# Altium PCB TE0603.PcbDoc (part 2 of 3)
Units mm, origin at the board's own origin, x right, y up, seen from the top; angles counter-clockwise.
Board outline 115 x 70 mm, 4 copper layers (L 01 (Top), L 02, L 03, L 04 (Bot)), stack 1.564 mm thick; 86 components, 166 nets, 587 pads, 211 vias.
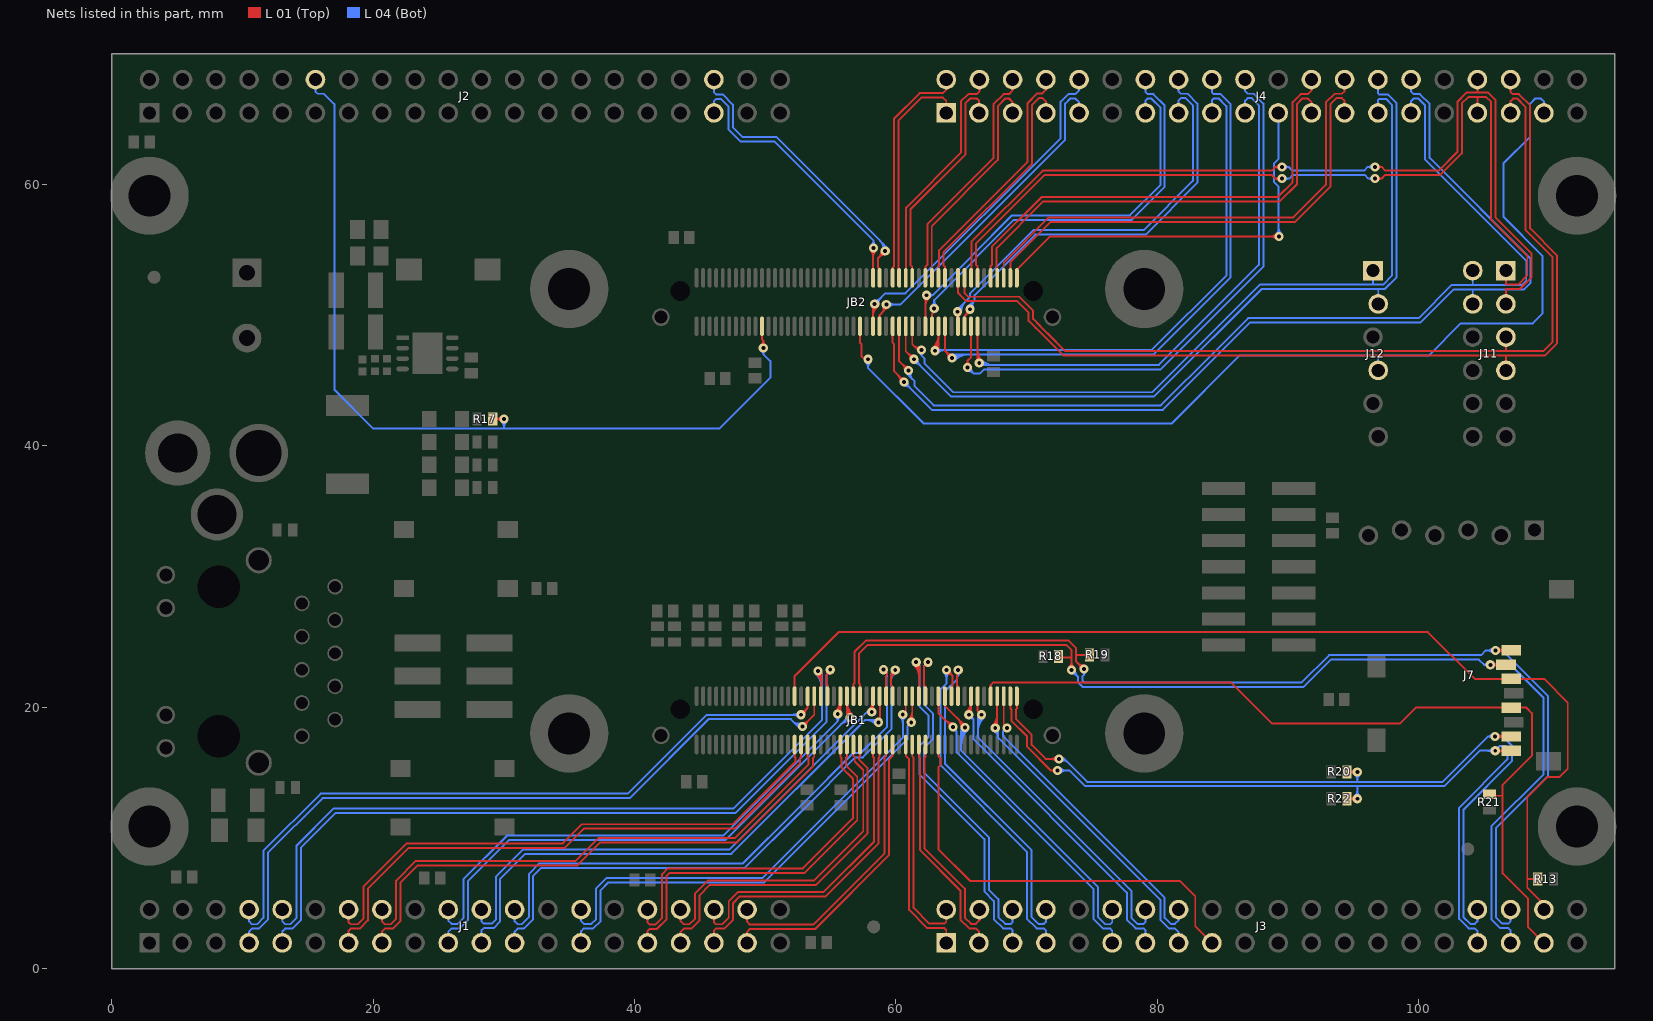
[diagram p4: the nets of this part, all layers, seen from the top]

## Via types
v1: diameter 0.7, hole 0.3, L 01 (Top) to L 04 (Bot), 211 vias

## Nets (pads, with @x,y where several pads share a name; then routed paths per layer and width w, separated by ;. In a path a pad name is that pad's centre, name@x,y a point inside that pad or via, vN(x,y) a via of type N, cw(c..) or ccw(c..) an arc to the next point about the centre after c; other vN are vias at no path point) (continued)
B2B_B0_L36_P: J4.37 J12.4 JB2.52 | length 82.7
  L 01 (Top) w0.15: JB2.52@57.25,48.85 57.25,47.894 57.365,47.78 57.365,46.86 57.6,46.625 v1(57.875,46.625) v1@57.865,46.635
  L 04 (Bot) w0.15: v1@57.681,46.431 cw(c57.211,45.961) 57.875,45.961 cw(c58.539,45.961) v1@58.069,46.431 ; v1(57.875,46.625) 57.875,45.95 62.115,41.71 81.091,41.71 86.281,46.9 96.9,46.9 ; J12.4@96.9,45.78 96.9,46.9 ; J4.37@109.571,65.479 109.571,66.354 109.35,66.575 108.9,66.575 108.515,66.19 108.515,63.665 106.49,61.64 106.49,57.51 109.465,54.535 109.465,50.109 108.731,49.375 103.231,49.375 100.756,46.9 96.9,46.9
B2B_B0_L37_N: J2.35 JB2.55 | length 23.6
  L 01 (Top) w0.15: v1@58.081,54.931 cw(c57.671,54.521) 58.25,54.521 ; JB2.55@58.25,52.85 v1@58.25,54.925 ; 58.25,54.401 cw(c58.999,54.401) v1@58.469,54.931 ; 58.25,54.763 cw(c58.637,54.763) v1@58.363,55.037
  L 04 (Bot) w0.15: J2.35@46.071,65.479 46.071,66.371 46.25,66.55 46.6,66.55 47.185,65.965 47.185,64.219 48.129,63.275 50.725,63.275 58.275,55.725 ; v1@58.095,55.333 ccw(c57.758,55.725) 58.275,55.725 ; v1(58.275,55.125) 58.275,55.725 ; v1@58.455,55.333 cw(c58.792,55.725) 58.275,55.725
B2B_B0_L37_P: J2.36 JB2.57 | length 25.6
  L 01 (Top) w0.15: JB2.57@58.75,52.55 JB2.57@58.75,52.85 58.711,52.889 58.711,53.575 58.635,53.652 58.635,54.36 v1(59.178,54.903) ; v1@58.903,54.903 cw(c58.239,54.903) 58.708,54.433 cw(c59.178,53.964) v1@59.178,54.628
  L 04 (Bot) w0.15: J2.36@46.071,68.019 46.071,67.069 46.25,66.89 46.741,66.89 47.525,66.106 47.525,64.359 48.269,63.615 50.866,63.615 58.765,55.716 ; 58.765,55.71 v1@59.228,55.247 ; 58.787,55.688 cw(c58.126,55.028) v1@59.054,54.917 ; 59.005,55.47 cw(c58.516,54.981) v1@59.203,54.9 ; 59.224,55.251 cw(c58.907,54.935) v1@59.352,54.882
B2B_B0_L38_N: J4.2 JB2.61 | length 18.2
  L 01 (Top) w0.15: JB2.61@59.75,52.55 59.75,53.63 59.868,53.748 59.868,54.257 59.865,54.26 59.865,65.046 61.809,66.99 63.6,66.99 63.851,67.241 J4.2@63.851,68.019
B2B_B0_L38_P: J4.1 JB2.63 | length 17.8
  L 01 (Top) w0.15: JB2.63@60.25,52.55 60.25,53.383 60.205,53.428 60.205,53.604 60.208,53.607 60.208,54.398 60.205,54.401 60.205,64.905 61.95,66.65 63.6,66.65 63.851,66.399 J4.1@63.851,65.479
B2B_B0_L49_N: J4.9 JB2.58 | length 28.6
  L 01 (Top) w0.15: JB2.58@58.75,48.85 58.75,50 59.265,50.515 v1(59.265,50.823) ; 58.904,50.154 ccw(c58.544,50.514) v1@59.012,50.715 ; 59.061,50.311 ccw(c58.764,50.608) v1@59.15,50.774 ; 59.218,50.468 ccw(c58.983,50.702) v1@59.288,50.833
  L 04 (Bot) w0.15: v1(59.265,50.823) 60.354,50.823 72.94,63.409 72.94,66.19 73.325,66.575 73.725,66.575 74.011,66.289 J4.9@74.011,65.479 ; v1@59.459,50.629 cw(c59.929,50.159) 59.929,50.823 cw(c59.929,51.487) v1@59.459,51.018
B2B_B0_L49_P: J4.10 JB2.56 | length 29.6
  L 01 (Top) w0.15: v1@58.181,50.656 cw(c58.012,50.487) 58.25,50.487 ; JB2.56@58.25,48.85 58.25,50.725 v1(58.375,50.85) ; JB2.56@58.25,49.885 cw(c59.34,49.885) v1@58.569,50.656 ; 58.25,50.247 cw(c58.978,50.247) v1@58.463,50.762
  L 04 (Bot) w0.15: v1(58.375,50.85) 59.19,51.665 60.715,51.665 72.6,63.55 72.6,66.331 73.184,66.915 73.725,66.915 74.011,67.201 J4.10@74.011,68.019 ; v1@58.375,51.125 ccw(c58.375,51.789) 58.844,51.319 ccw(c59.314,50.85) v1@58.65,50.85
B2B_B0_L50_N: J4.4 JB2.65 | length 18.2
  L 01 (Top) w0.15: JB2.65@60.75,52.55 60.75,53.383 60.773,53.406 60.773,58.223 64.975,62.425 64.975,66.356 65.534,66.915 66.2,66.915 66.391,67.106 J4.4@66.391,68.019
B2B_B0_L50_P: J4.3 JB2.67 | length 17.7
  L 01 (Top) w0.15: JB2.67@61.25,52.55 JB2.67@61.25,52.85 61.25,53.688 61.113,53.825 61.113,58.082 65.315,62.284 65.315,66.215 65.675,66.575 66.2,66.575 66.351,66.424 J4.3@66.351,65.479
B2B_B0_L51_N: J4.6 JB2.71 | length 18.5
  L 01 (Top) w0.15: JB2.71@62.25,52.85 62.25,53.7 62.4,53.85 62.4,56.956 67.46,62.016 67.46,66.141 68.234,66.915 68.65,66.915 68.931,67.196 J4.6@68.931,68.019 ; JB2.71@62.25,52.55 JB2.71@62.25,52.85
B2B_B0_L51_P: J4.5 JB2.73 | length 17.9
  L 01 (Top) w0.15: JB2.73@62.75,52.55 62.75,53.383 62.74,53.393 62.74,56.815 67.8,61.875 67.8,66 68.375,66.575 68.65,66.575 68.931,66.294 J4.5@68.931,65.479
B2B_B0_L62_N: J4.29 J11.2 JB2.64 | length 79.1
  L 01 (Top) w0.15: JB2.64@60.25,48.85 60.25,46.48 v1(60.953,45.777) ; v1@60.678,45.777 ccw(c60.014,45.777) 60.484,46.247 ccw(c60.953,46.716) v1@60.953,46.052
  L 04 (Bot) w0.15: v1@60.932,45.79 ccw(c61.205,45.623) 60.978,45.397 ; v1(60.953,45.777) 60.953,45.422 ; v1@61.06,45.712 ccw(c61.371,45.521) 61.113,45.262 ; v1@61.187,45.634 ccw(c61.538,45.419) 61.247,45.128 ; J4.29@99.411,65.479 99.411,66.386 99.6,66.575 99.95,66.575 100.485,66.04 100.485,61.896 108.225,54.156 108.225,52.625 107.915,52.315 102.54,52.315 99.99,49.765 86.94,49.765 84.34,47.165 80.275,43.1 62.886,43.1 61.425,44.561 61.425,44.95 60.953,45.422 ; 104.13,52.37 J11.2@104.13,53.4 ; 60.953,45.422 cw(c61.045,45.422) 61.022,45.511 ccw(c61.045,45.422) 60.953,45.422 ; 60.953,45.422 ccw(c60.861,45.422) 60.884,45.511 cw(c60.861,45.422) 60.953,45.422
B2B_B0_L62_P: J4.30 J11.4 JB2.62 | length 80.4
  L 01 (Top) w0.15: JB2.62@59.75,48.85 59.75,47.894 59.865,47.78 59.865,45.71 60.482,45.093 60.482,45.068 60.628,44.922 v1(60.628,44.877) ; 60.109,45.466 cw(c59.52,44.877) v1@60.353,44.877 ; 60.278,45.297 ccw(c60.628,45.647) v1@60.628,45.152 ; 60.365,45.21 cw(c60.033,44.877) v1@60.503,44.877
  L 04 (Bot) w0.15: v1@60.628,44.602 cw(c60.628,43.938) 61.097,44.408 cw(c61.567,44.877) v1@60.903,44.877 ; v1(60.628,44.877) 62.745,42.76 80.416,42.76 87.081,49.425 100.131,49.425 102.681,51.975 104.125,51.975 ; J4.30@99.411,68.019 99.411,67.104 99.6,66.915 100.091,66.915 100.825,66.181 100.825,62.037 108.565,54.297 108.565,52.484 108.056,51.975 104.125,51.975 ; J11.4@104.13,50.86 104.13,51.97 104.125,51.975
B2B_B0_L63_N: J4.8 JB2.75 | length 19.1
  L 01 (Top) w0.15: JB2.75@63.25,52.55 JB2.75@63.25,52.85 63.25,53.805 63.295,53.85 63.295,54.945 63.31,54.96 70.075,61.725 70.075,66.231 70.809,66.965 71.2,66.965 71.471,67.236 J4.8@71.471,68.019
B2B_B0_L63_P: J4.7 JB2.77 | length 18.7
  L 01 (Top) w0.15: JB2.77@63.75,52.55 JB2.77@63.75,52.85 63.75,53.71 63.635,53.825 63.635,54.804 70.415,61.584 70.415,66.09 70.95,66.625 71.2,66.625 71.471,66.354 J4.7@71.471,65.479
B2B_B0_L64_N: J4.36 J11.7 JB2.81 | length 72.5
  L 01 (Top) w0.15: JB2.81@64.75,52.55 64.75,51.708 64.885,51.573 64.885,51.567 65.384,51.067 69.277,51.067 70.155,50.189 70.155,49.57 70.695,49.03 70.695,49.02 71.445,48.27 71.455,48.27 72.825,46.9 106.65,46.9 ; J11.7@106.67,45.78 106.67,46.88 106.65,46.9 ; J4.36@107.031,68.019 107.031,67.069 107.185,66.915 107.662,66.915 108.515,66.062 108.515,56.64 110.575,54.581 110.575,47.819 109.656,46.9 106.65,46.9
B2B_B0_L64_P: J4.35 J11.5 JB2.83 | length 70.7
  L 01 (Top) w0.15: JB2.83@65.25,52.55 65.25,51.682 65.525,51.407 69.418,51.407 70.495,50.33 70.495,49.711 71.035,49.171 71.035,49.161 71.586,48.61 71.596,48.61 72.966,47.24 106.675,47.24 ; J11.5@106.67,48.32 106.67,47.245 106.675,47.24 ; J4.35@107.031,65.479 107.031,66.381 107.225,66.575 107.521,66.575 108.175,65.921 108.175,56.5 110.235,54.44 110.235,47.96 109.515,47.24 106.675,47.24
B2B_B0_L65_N: J4.34 J11.3 JB2.85 | length 72.7
  L 01 (Top) w0.15: JB2.85@65.75,52.55 65.795,52.595 65.795,53.704 65.773,53.726 65.773,55.604 71.234,61.065 88.765,61.065 89.04,61.34 ; v1@89.289,61.199 ccw(c89.04,61.05) 89.04,61.34 ; v1@89.289,61.481 cw(c89.04,61.63) 89.04,61.34 ; v1(89.525,61.34) 89.04,61.34 ; v1(96.65,61.34) 97.16,61.34 ; v1@96.88,61.189 cw(c97.16,61.005) 97.16,61.34 ; v1@96.88,61.491 ccw(c97.16,61.675) 97.16,61.34 ; 104.491,67.035 J4.34@104.491,68.019 ; J11.3@106.67,50.86 106.67,51.995 ; 106.675,52 107.741,52 108.64,52.899 108.64,54.691 105.875,57.456 105.875,66.456 105.306,67.025 103.65,67.025 102.966,66.341 102.966,62.516 101.515,61.065 97.435,61.065 97.16,61.34
  L 04 (Bot) w0.15: v1(89.525,61.34) 90.035,61.34 ; v1@89.755,61.189 cw(c90.035,61.005) 90.035,61.34 ; v1@89.755,61.491 ccw(c90.035,61.675) 90.035,61.34 ; v1@96.426,61.18 ccw(c96.115,60.957) 96.115,61.34 ; v1@96.426,61.5 cw(c96.115,61.723) 96.115,61.34 ; v1(96.65,61.34) 96.115,61.34 ; 90.035,61.34 90.31,61.065 95.84,61.065 96.115,61.34
B2B_B0_L65_P: J4.33 J11.1 JB2.87 | length 71.2
  L 01 (Top) w0.15: JB2.87@66.25,52.55 JB2.87@66.25,53.369 ; JB2.87@66.256,53.375 66.256,53.725 66.113,53.867 66.113,55.463 71.375,60.725 88.735,60.725 89.01,60.45 ; v1@89.296,60.297 ccw(c89.01,60.105) 89.01,60.45 ; v1@89.296,60.603 cw(c89.01,60.795) 89.01,60.45 ; v1(89.525,60.45) 89.01,60.45 ; v1(96.65,60.45) 97.15,60.45 ; v1@96.882,60.303 cw(c97.15,60.133) 97.15,60.45 ; v1@96.882,60.597 ccw(c97.15,60.767) 97.15,60.45 ; 103.3,62.369 101.656,60.725 97.425,60.725 97.15,60.45 ; 103.306,62.375 103.306,66.2 103.791,66.685 105.165,66.685 105.535,66.315 105.535,57.315 108.3,54.55 108.3,53.04 107.6,52.34 106.675,52.34 ; J4.33@104.491,65.479 104.491,66.676 ; 106.67,52.345 J11.1@106.67,53.4
  L 04 (Bot) w0.15: v1(89.525,60.45) 90.075,60.45 ; v1@89.745,60.285 cw(c90.075,60.038) 90.075,60.45 ; v1@89.745,60.615 ccw(c90.075,60.862) 90.075,60.45 ; v1@96.418,60.303 ccw(c96.15,60.133) 96.15,60.45 ; v1@96.418,60.597 cw(c96.15,60.767) 96.15,60.45 ; v1(96.65,60.45) 96.15,60.45 ; 90.075,60.45 90.35,60.725 95.875,60.725 96.15,60.45
B2B_B0_L66_N: J4.27 J12.1 JB2.68 | length 61.5
  L 01 (Top) w0.15: JB2.68@61.25,48.85 61.25,47.775 61.7,47.325 v1(61.95,47.325) ; 61.375,47.65 ccw(c61.657,47.932) v1@61.83,47.573 ; 61.525,47.5 ccw(c61.754,47.73) v1@61.896,47.438
  L 04 (Bot) w0.15: v1(61.95,47.325) 61.95,46.92 ; J12.1@96.5,53.4 96.5,52.34 ; J4.27@96.871,65.479 96.871,66.446 96.975,66.55 97.494,66.55 97.95,66.094 97.95,53.015 97.275,52.34 96.5,52.34 ; 61.95,46.92 cw(c62.111,46.92) 62.052,47.069 ccw(c62.111,46.92) 61.95,46.92 ; 61.95,46.92 ccw(c61.789,46.92) 61.848,47.069 cw(c61.789,46.92) 61.95,46.92 ; 61.95,46.92 62.175,46.695 62.175,46.306 64.381,44.1 79.594,44.1 87.834,52.34 96.5,52.34
B2B_B0_L66_P: J4.28 J12.2 JB2.66 | length 63.7
  L 01 (Top) w0.15: JB2.66@60.75,48.85 60.75,47.25 v1(61.375,46.625) ; v1@61.1,46.625 ccw(c60.436,46.625) 60.906,47.094 ccw(c61.375,47.564) v1@61.375,46.9
  L 04 (Bot) w0.15: v1@61.375,46.35 cw(c61.375,45.686) 61.844,46.156 cw(c62.314,46.625) v1@61.65,46.625 ; v1(61.375,46.625) 64.24,43.76 79.735,43.76 80.425,44.45 87.975,52 97.416,52 98.29,52.874 98.29,66.235 97.635,66.89 96.975,66.89 96.871,66.994 J4.28@96.871,68.019 ; J12.2@96.9,50.86 96.9,51.95
B2B_B1_L9_N: J4.18 JB2.78 | length 46.6
  L 01 (Top) w0.15: JB2.78@63.75,48.85 63.75,47.275 v1(64.3,46.725) ; v1@64.025,46.725 ccw(c63.361,46.725) 63.831,47.194 ccw(c64.3,47.664) v1@64.3,47
  L 04 (Bot) w0.15: v1@64.176,46.849 cw(c64.541,46.484) 64.541,47 ; v1@64.282,46.743 cw(c64.904,46.121) 64.904,47 ; v1(64.3,46.725) 64.575,47 79.731,47 85.615,52.884 85.615,66.141 84.841,66.915 84.3,66.915 84.171,67.044 J4.18@84.171,68.019 ; v1@64.388,46.637 cw(c65.266,45.759) 65.266,47 ; v1@64.494,46.531 cw(c65.628,45.397) 65.628,47
B2B_B1_L9_P: J4.17 JB2.76 | length 45.9
  L 01 (Top) w0.15: v1@62.806,47.469 ccw(c61.732,48.543) JB2.76@63.25,48.543 ; v1@62.912,47.363 ccw(c62.094,48.181) 63.25,48.181 ; v1(63,47.275) 63.025,47.275 63.25,47.5 JB2.76@63.25,48.85 ; v1@63.018,47.257 ccw(c62.456,47.819) 63.25,47.819
  L 04 (Bot) w0.15: v1(63,47.275) 63.065,47.34 64.25,47.34 79.59,47.34 85.275,53.025 85.275,66 84.7,66.575 84.3,66.575 84.171,66.446 J4.17@84.171,65.479 ; v1@63.088,47.187 cw(c63.459,46.816) 63.459,47.34 ; v1@63.194,47.081 cw(c63.821,46.454) 63.821,47.34 ; v1@63.194,47.469 ccw(c63.507,47.782) 63.507,47.34
B2B_B1_L10_N: J4.14 JB2.74 | length 34.3
  L 01 (Top) w0.15: JB2.74@62.75,48.85 62.75,50.075 62.95,50.274 62.95,50.5 62.948,50.502 v1(62.928,50.502)
  L 04 (Bot) w0.15: v1@62.738,50.701 ccw(c62.308,51.148) 62.928,51.148 ; v1(62.928,50.502) 62.948,50.502 62.95,50.5 62.95,50.274 62.928,50.252 62.928,51.148 ; v1@63.119,50.701 cw(c63.548,51.148) 62.928,51.148 ; J4.14@79.091,68.019 79.091,67.074 79.25,66.915 79.691,66.915 80.565,66.041 80.565,59.809 78.046,57.29 69.021,57.29 66.113,54.382 66.113,54.333 62.928,51.148
B2B_B1_L10_P: J4.13 JB2.72 | length 34.7
  L 01 (Top) w0.15: v1@62.156,51.331 cw(c61.928,51.103) 62.25,51.103 ; JB2.72@62.25,49.15 62.25,51.325 62.425,51.5 62.375,51.5 v1(62.35,51.525) ; 62.25,50.62 cw(c63.255,50.62) v1@62.544,51.331 ; 62.25,50.982 cw(c62.893,50.982) v1@62.438,51.437 ; JB2.72@62.25,48.85 JB2.72@62.25,49.15
  L 04 (Bot) w0.15: v1(62.35,51.525) 62.824,51.525 ; v1@62.589,51.388 cw(c62.824,51.253) 62.824,51.525 ; v1@62.589,51.662 ccw(c62.824,51.797) 62.824,51.525 ; J4.13@79.091,65.479 79.091,66.416 79.25,66.575 79.55,66.575 80.225,65.9 80.225,59.95 77.905,57.63 68.88,57.63 65.773,54.523 65.773,54.474 62.824,51.525
B2B_B1_L19_N: J4.25 JB2.97 | length 37
  L 01 (Top) w0.15: JB2.97@68.75,52.55 JB2.97@68.75,52.85 68.75,54.044 71.841,57.135 90.541,57.135 93.24,59.834 93.24,66.14 93.7,66.6 94.125,66.6 94.331,66.394 J4.25@94.331,65.479
B2B_B1_L19_P: J4.26 JB2.95 | length 37.6
  L 01 (Top) w0.15: JB2.95@68.25,52.55 68.25,52.85 68.25,54.025 71.7,57.475 90.4,57.475 92.9,59.975 92.9,66.281 93.559,66.94 94.125,66.94 94.331,67.146 J4.26@94.331,68.019
B2B_B1_L20_N: J4.23 JB2.93 | length 36
  L 01 (Top) w0.15: JB2.93@67.75,52.55 67.75,53.383 67.705,53.428 67.705,55.124 71.281,58.7 89.356,58.7 90.69,60.034 90.69,66.165 91.1,66.575 91.525,66.575 91.791,66.309 J4.23@91.791,65.479
B2B_B1_L20_P: J4.24 JB2.91 | length 36.6
  L 01 (Top) w0.15: JB2.91@67.25,52.85 67.25,53.76 67.365,53.875 67.365,55.265 71.14,59.04 89.215,59.04 90.35,60.175 90.35,66.306 90.959,66.915 91.525,66.915 91.791,67.181 J4.24@91.791,68.019 ; JB2.91@67.25,52.55 JB2.91@67.25,52.85
B2B_B1_L21_N: J4.15 JB2.82 | length 34.6
  L 01 (Top) w0.15: v1@64.524,50.068 cw(c64.03,49.575) JB2.82@64.728,49.575 ; v1(64.718,50.263) 64.728,50.252 64.728,48.872 JB2.82@64.75,48.85 ; JB2.82@64.728,49.623 cw(c65.358,49.623) v1@64.913,50.068
  L 04 (Bot) w0.15: v1(64.718,50.263) 64.728,50.252 64.728,50.45 65.653,51.375 65.653,51.644 70.514,56.505 78.955,56.505 82.725,60.275 82.725,66.05 82.175,66.6 81.8,66.6 81.631,66.431 J4.15@81.631,65.479 ; v1@64.718,50.538 ccw(c64.718,50.774) 64.885,50.607 ; v1@64.843,50.263 cw(c65.572,50.263) 65.057,50.779 ; v1@64.993,50.263 cw(c66.084,50.263) 65.313,51.035
B2B_B1_L21_P: J4.16 JB2.84 | length 35.8
  L 01 (Top) w0.15: JB2.84@65.25,48.85 65.26,48.86 65.26,49.915 65.25,49.925 65.552,50.227 65.628,50.227 65.65,50.206 65.65,50.203 65.653,50.203 65.653,50.252 65.725,50.181 65.725,50.165 65.71,50.165 65.678,50.197 v1(65.678,50.452) ; 65.3,49.975 ccw(c64.997,50.278) v1@65.412,50.384 ; 65.378,50.053 cw(c65.678,49.753) v1@65.678,50.177
  L 04 (Bot) w0.15: v1@65.656,50.442 cw(c65.979,50.597) 65.725,50.85 ; v1(65.678,50.452) 65.678,50.197 65.694,50.197 65.694,50.211 65.653,50.252 65.653,50.203 65.65,50.203 65.65,50.206 65.628,50.227 65.628,50.753 66.025,51.15 ; v1@65.791,50.507 cw(c66.182,50.694) 65.875,51 ; v1@65.926,50.571 cw(c66.384,50.791) 66.025,51.15 ; J4.16@81.631,68.019 81.631,67.109 81.8,66.94 82.316,66.94 83.065,66.191 83.065,60.134 79.096,56.165 70.655,56.165 66.025,51.535 66.025,51.15
B2B_B1_L59: J4.21 JB2.99 | length 34.2
  L 01 (Top) w0.15: JB2.99@69.25,52.55 69.25,53.475 71.8,56.025 v1(89.3,56.025) ; v1@89.106,55.831 ccw(c88.636,55.361) 88.636,56.025 ccw(c88.636,56.689) v1@89.106,56.219
  L 04 (Bot) w0.15: v1@89.106,56.219 ccw(c88.696,56.629) 89.275,56.629 ; J4.21@89.251,65.479 89.275,65.455 89.275,61.96 88.91,61.595 88.91,60.195 89.275,59.83 v1@89.275,56.025 ; 89.275,56.387 ccw(c89.662,56.387) v1@89.388,56.113 ; 89.275,56.749 ccw(c90.024,56.749) v1@89.494,56.219
B2B_B1_L61_N: J4.19 JB2.88 | length 45.1
  L 01 (Top) w0.15: v1@66.181,46.544 ccw(c66.012,46.713) 66.25,46.713 ; 66.25,46.953 ccw(c66.978,46.953) v1@66.463,46.438 ; 66.25,47.315 ccw(c67.34,47.315) v1@66.569,46.544 ; JB2.88@66.25,48.85 66.25,46.475 v1(66.375,46.35)
  L 04 (Bot) w0.15: v1@66.357,46.332 ccw(c66.701,46.676) 66.701,46.19 ; v1@66.463,46.438 ccw(c67.063,47.038) 67.063,46.19 ; v1@66.535,46.19 80.115,46.19 87.775,53.85 87.775,66.05 87.225,66.6 86.9,66.6 86.711,66.411 J4.19@86.711,65.479 ; v1@66.569,46.544 ccw(c67.425,47.4) 67.425,46.19
B2B_B1_L61_P: J4.20 JB2.86 | length 45.9
  L 01 (Top) w0.15: v1@65.328,46.232 ccw(c65.158,46.5) 65.475,46.5 ; v1(65.475,46) 65.475,46.5 ; v1@65.622,46.232 cw(c65.792,46.5) 65.475,46.5 ; JB2.86@65.75,48.85 65.75,46.775 65.475,46.5
  L 04 (Bot) w0.15: v1(65.475,46) 65.925,45.55 ; v1@65.483,45.725 cw(c65.502,45.127) 65.925,45.55 ; v1@65.75,45.992 ccw(c66.348,45.973) 65.925,45.55 ; J4.20@86.711,68.019 86.711,67.129 86.9,66.94 87.366,66.94 88.115,66.191 88.115,53.709 80.256,45.85 66.745,45.85 66.445,45.55 65.925,45.55
B2B_B2_L2_N: J3.33 J7.8 JB1.97 R22.2 | length 69.6
  L 01 (Top) w0.15: JB1.97@68.75,20.75 68.75,19.906 68.83,19.826 68.83,19.014 ; 68.83,18.969 70.035,17.764 70.035,16.99 71.865,15.16 ; v1@72.145,15.009 ccw(c71.865,14.825) 71.865,15.16 ; v1@72.145,15.311 cw(c71.865,15.495) 71.865,15.16 ; v1(72.375,15.16) 71.865,15.16 ; v1@95.106,12.806 ccw(c94.636,12.336) 94.636,13 ccw(c94.636,13.664) v1@95.106,13.194 ; v1(105.85,16.675) 107.065,16.675 J7.8@107.075,16.665 ; v1@106.044,16.481 cw(c106.514,16.011) 106.514,16.675 cw(c106.514,17.339) v1@106.044,16.869
  L 04 (Bot) w0.15: v1(72.375,15.16) 73.29,15.16 74.49,13.96 101.966,13.96 104.681,16.675 v1(105.85,16.675) 106.21,17.035 ; v1@72.569,14.966 cw(c73.039,14.496) 73.039,15.16 cw(c73.039,15.824) v1@72.569,15.354 ; v1@95.106,13.194 ccw(c94.636,13.664) 95.3,13.664 ccw(c95.964,13.664) v1@95.494,13.194 ; v1(95.3,13) 95.3,13.9 ; J3.33@104.491,1.979 104.491,2.894 104.3,3.085 103.809,3.085 103.085,3.809 103.085,12.31 106.785,16.01 106.785,16.89 106.64,17.035 106.21,17.035 ; v1@105.656,16.481 ccw(c105.186,16.011) 105.186,16.675 ccw(c105.186,17.339) v1@105.656,16.869 ; v1@105.906,16.944 ccw(c105.974,17.27) 106.21,17.035 ; v1@106.119,16.731 cw(c106.445,16.799) 106.21,17.035
B2B_B2_L2_P: J3.34 J7.7 JB1.99 R20.2 | length 70.9
  L 01 (Top) w0.15: JB1.99@69.25,20.75 69.25,19.906 69.17,19.826 69.17,19.11 70.375,17.905 70.375,17.131 71.456,16.05 v1@72.478,16.05 ; 71.813,16.05 ccw(c71.813,16.717) v1@72.284,16.245 ; 71.817,16.05 cw(c71.817,15.389) v1@72.284,15.856 ; R20.2@94.51,15.05 v1(95.3,15.05) ; v1@95.106,14.856 ccw(c94.636,14.386) 94.636,15.05 ccw(c94.636,15.714) v1@95.106,15.244 ; v1(105.825,17.775) 107.065,17.775 J7.7@107.075,17.765 ; v1@106.019,17.581 cw(c106.489,17.111) 106.489,17.775 cw(c106.489,18.439) v1@106.019,17.969
  L 04 (Bot) w0.15: v1@72.461,16.069 cw(c72.662,15.862) 72.865,16.066 ; v1(72.479,16.051) 72.88,16.051 ; v1@72.566,15.961 cw(c72.768,15.752) 72.973,15.958 ; v1@72.67,15.853 cw(c72.874,15.643) 73.081,15.85 ; v1@72.735,15.951 cw(c72.88,15.895) 72.88,16.051 ; v1@72.735,16.15 ccw(c72.88,16.206) 72.88,16.051 ; v1@95.106,14.856 cw(c94.636,14.386) 95.3,14.386 cw(c95.964,14.386) v1@95.494,14.856 ; 95.3,14.38 v1(95.3,15.05) ; J3.34@104.491,4.519 104.491,3.616 104.3,3.425 103.95,3.425 103.425,3.95 103.425,12.169 107.125,15.869 107.125,17.075 106.425,17.775 ; v1@105.599,17.618 ccw(c105.3,17.411) 105.3,17.775 ; v1@105.599,17.932 cw(c105.3,18.139) 105.3,17.775 ; v1@106.033,17.595 cw(c106.425,17.258) 106.425,17.775 ; v1@106.033,17.955 ccw(c106.425,18.292) 106.425,17.775 ; 72.88,16.051 74.631,14.3 101.825,14.3 105.3,17.775 ; 105.3,17.775 v1(105.825,17.775) 106.425,17.775
B2B_B2_L4_N: J3.13 JB1.85 | length 27.6
  L 01 (Top) w0.15: v1@65.381,19.619 ccw(c64.488,20.512) JB1.85@65.75,20.512 ; v1@65.487,19.513 ccw(c64.85,20.15) JB1.85@65.75,20.15 ; v1(65.575,19.425) 65.75,19.6 JB1.85@65.75,20.75 ; v1@65.593,19.407 ccw(c65.212,19.788) 65.75,19.788
  L 04 (Bot) w0.15: v1(65.575,19.425) 65.937,19.063 ; v1@65.63,19.155 cw(c65.697,18.822) 65.937,19.063 ; v1@65.845,19.37 ccw(c66.178,19.303) 65.937,19.063 ; J3.13@79.091,1.979 79.091,2.944 78.95,3.085 78.334,3.085 77.675,3.744 77.675,5.819 65.937,17.557 65.937,19.063
B2B_B2_L4_P: J3.14 JB1.87 | length 27.5
  L 01 (Top) w0.15: JB1.87@66.25,20.75 66.25,19.725 v1(66.55,19.425)
  L 04 (Bot) w0.15: 66.277,18.103 cw(c67.872,18.103) v1@66.744,19.231 ; 66.277,18.465 cw(c67.51,18.465) v1@66.638,19.337 ; 66.277,18.827 cw(c67.148,18.827) v1@66.532,19.443 ; 66.277,19.189 cw(c66.786,19.189) v1@66.426,19.549 ; v1(66.55,19.425) 66.277,19.152 66.277,17.698 78.015,5.96 78.015,3.885 78.475,3.425 78.95,3.425 79.091,3.566 J3.14@79.091,4.519
B2B_B2_L5_N: J3.12 JB1.77 | length 29.3
  L 01 (Top) w0.15: JB1.77@63.75,20.75 63.75,20.125 65.195,18.68 65.195,18.475 65.225,18.475 65.275,18.425 65.278,18.428 v1(65.278,18.451) ; 64.706,19.169 cw(c63.987,18.451) v1@65.003,18.451 ; 64.962,18.913 cw(c64.499,18.451) v1@65.153,18.451 ; 65.058,18.817 ccw(c65.278,19.038) v1@65.278,18.726
  L 04 (Bot) w0.15: 64.99,17.091 cw(c66.638,17.091) v1@65.473,18.256 ; 64.99,17.453 cw(c66.276,17.453) v1@65.367,18.363 ; 64.99,17.816 cw(c65.914,17.816) v1@65.261,18.469 ; 64.99,18.178 cw(c65.551,18.178) v1@65.154,18.575 ; v1(65.278,18.451) 65.278,18.428 64.99,18.14 64.99,16.691 75.465,6.216 75.465,3.935 76,3.4 76.4,3.4 76.551,3.551 J3.12@76.551,4.519
B2B_B2_L5_P: J3.11 JB1.75 | length 26.7
  L 01 (Top) w0.15: JB1.75@63.25,20.75 63.25,19.55 64.375,18.425 64.425,18.475 64.425,18.5 64.424,18.501 v1(64.378,18.501) ; 63.774,19.026 ccw(c64.378,19.631) v1@64.378,18.776 ; 63.965,18.835 cw(c63.63,18.501) v1@64.103,18.501 ; 64.03,18.77 ccw(c64.378,19.119) v1@64.378,18.626
  L 04 (Bot) w0.15: v1(64.378,18.501) 64.424,18.501 64.425,18.5 64.425,18.475 64.375,18.425 64.65,18.15 64.65,16.55 75.125,6.075 75.125,3.794 75.859,3.06 76.4,3.06 76.551,2.909 J3.11@76.551,1.979 ; v1@64.446,18.234 cw(c64.489,18.068) 64.61,18.19 cw(c64.691,18.27) v1@64.599,18.338
B2B_B2_L6_N: J3.6 JB1.71 | length 27.8
  L 01 (Top) w0.15: JB1.71@62.25,20.75 62.25,21.575 62.135,21.69 62.135,23.135 v1(62.45,23.45)
  L 04 (Bot) w0.15: v1(62.45,23.45) 62.135,23.135 62.135,20.216 62.82,19.531 62.82,17.552 62.135,16.868 62.135,15.021 67.105,10.051 67.105,6.051 67.84,5.316 67.84,3.935 68.35,3.425 68.8,3.425 68.931,3.556 J3.6@68.931,4.519
B2B_B2_L6_P: J3.5 JB1.69 | length 31.1
  L 01 (Top) w0.15: v1@61.356,23.256 cw(c60.294,22.194) 61.795,22.194 ; v1@61.462,23.362 cw(c60.656,22.556) 61.795,22.556 ; v1(61.55,23.45) 61.795,23.205 61.795,21.62 61.75,21.575 61.75,20.75 JB1.69@61.825,20.825 ; v1@61.568,23.468 cw(c61.018,22.918) 61.795,22.918
  L 04 (Bot) w0.15: v1(61.55,23.45) 61.795,23.205 61.795,20.075 62.48,19.391 62.48,17.693 61.795,17.008 61.795,14.88 66.765,9.91 66.765,5.91 67.5,5.175 67.5,3.794 68.209,3.085 68.8,3.085 68.931,2.954 J3.5@68.931,1.979
B2B_B2_L8_N: J1.24 JB1.59 | length 44.5
  L 01 (Top) w0.15: v1(59.05,22.875) 59.33,22.595 59.33,22.481 59.25,22.401 JB1.59@59.25,20.75
  L 04 (Bot) w0.15: J1.24@30.831,4.519 30.831,3.619 31.05,3.4 31.375,3.4 31.91,3.935 31.91,7.241 32.719,8.05 48.3,8.05 52.245,11.995 ; 52.245,11.996 52.804,12.555 56.753,16.503 57.328,16.503 59.325,18.5 59.325,21.524 59.298,21.551 59.298,22.347 59.325,22.374 59.325,22.6 v1(59.05,22.875)
B2B_B2_L8_P: J1.23 JB1.61 | length 47.9
  L 01 (Top) w0.15: 59.67,22.268 cw(c59.978,22.268) v1@59.963,22.575 ; 59.67,22.426 cw(c59.97,22.426) v1@59.956,22.725 ; 59.67,22.583 cw(c59.963,22.583) v1@59.949,22.875 ; JB1.61@59.75,20.75 59.75,21.584 59.638,21.696 59.638,22.308 59.67,22.34 59.67,22.57 v1(59.95,22.85)
  L 04 (Bot) w0.15: J1.23@30.831,1.979 30.831,2.841 31.05,3.06 31.516,3.06 32.25,3.794 32.25,7.1 32.86,7.71 48.441,7.71 52.585,11.854 52.945,12.215 56.894,16.163 57.469,16.163 59.675,18.369 59.675,21.659 59.638,21.696 59.638,22.206 59.675,22.243 59.675,22.575 v1(59.95,22.85) ; 59.675,22.184 cw(c60.079,22.184) v1@60.002,22.58 ; 59.675,22.365 cw(c60.044,22.365) v1@59.974,22.727 ; 59.675,22.547 cw(c60.009,22.547) v1@59.945,22.875
B2B_B2_L9_N: J3.7 JB1.79 | length 29.1
  L 01 (Top) w0.15: v1(63.875,22.85) 64.33,22.395 ; v1@63.881,22.575 cw(c63.895,21.959) 64.33,22.395 ; v1@64.15,22.844 ccw(c64.766,22.83) 64.33,22.395 ; JB1.79@64.25,20.75 64.25,21.581 64.33,21.661 64.33,22.395
  L 04 (Bot) w0.15: v1@63.681,22.656 cw(c63.211,22.186) 63.875,22.186 cw(c64.539,22.186) v1@64.069,22.656 ; v1(63.875,22.85) 63.875,21.824 63.415,21.364 63.415,15.554 70.025,8.944 70.025,3.819 70.759,3.085 71.325,3.085 71.471,2.939 J3.7@71.471,1.979
B2B_B2_L9_P: J3.8 JB1.81 | length 26.9
  L 01 (Top) w0.15: v1@64.67,22.754 64.67,21.775 64.67,21.661 64.75,21.581 JB1.81@64.75,20.75
  L 04 (Bot) w0.15: v1@64.662,22.594 cw(c64.593,22.421) 64.779,22.421 ; v1(64.765,22.849) 64.779,22.835 64.779,22.421 ; v1@64.89,22.604 ccw(c64.984,22.421) 64.779,22.421 ; J3.8@71.471,4.519 71.471,3.571 71.325,3.425 70.9,3.425 70.365,3.96 70.365,9.085 63.755,15.695 63.755,21.223 64.688,22.156 64.688,22.331 64.779,22.421
B2B_B2_L10_N: J3.15 JB1.93 | length 28.1
  L 01 (Top) w0.15: v1@67.406,18.619 ccw(c66.573,19.452) 67.75,19.452 ; v1@67.512,18.513 ccw(c66.935,19.09) 67.75,19.09 ; v1(67.6,18.425) 67.75,18.575 JB1.93@67.75,20.75
  L 04 (Bot) w0.15: v1@67.484,18.176 cw(c67.237,17.642) 67.825,17.642 ; v1@67.547,18.312 cw(c67.346,17.877) 67.825,17.877 ; v1(67.6,18.425) 67.825,18.2 67.825,17.675 80.225,5.275 80.225,3.744 80.884,3.085 81.35,3.085 81.631,2.804 J3.15@81.631,1.979 ; v1@67.611,18.448 cw(c67.455,18.112) 67.825,18.112
B2B_B2_L10_P: J3.16 JB1.95 | length 24.5
  L 01 (Top) w0.15: JB1.95@68.25,20.75 68.25,18.625 68.45,18.425 68.451,18.426 v1(68.503,18.426)
  L 04 (Bot) w0.15: v1(68.503,18.426) 68.451,18.426 68.215,18.19 68.215,18.17 68.175,18.13 68.175,17.806 80.565,5.416 80.565,3.885 81.025,3.425 81.35,3.425 81.631,3.706 J3.16@81.631,4.519
B2B_B2_L11_N: J1.27 JB1.67 | length 38.2
  L 01 (Top) w0.15: v1@60.981,19.044 ccw(c60.329,19.696) 61.25,19.696 ; v1@61.087,18.938 ccw(c60.692,19.333) 61.25,19.333 ; v1(61.175,18.85) 61.25,18.925 JB1.67@61.25,20.75 ; 61.25,19.332 ccw(c61.657,19.332) v1@61.369,19.044
  L 04 (Bot) w0.15: J1.27@35.911,1.979 35.911,2.871 36.125,3.085 36.841,3.085 37.4,3.644 37.4,6 38.01,6.61 49.94,6.61 60.875,17.545 60.875,18.55 v1(61.175,18.85)
B2B_B2_L11_P: J1.28 JB1.65 | length 37.1
  L 01 (Top) w0.15: v1(60.525,19.46) 60.525,19.475 60.75,19.7 JB1.65@60.75,20.75
  L 04 (Bot) w0.15: J1.28@35.911,4.519 35.911,3.639 36.125,3.425 36.7,3.425 37.06,3.785 37.06,6.141 37.869,6.95 49.799,6.95 60.525,17.676 v1(60.525,19.46) v1@60.525,19.475 ; v1@60.331,19.266 cw(c59.861,18.796) 60.525,18.796 cw(c61.189,18.796) v1@60.719,19.266
B2B_B2_L15_N: J3.4 JB1.72 | length 16.7
  L 01 (Top) w0.15: JB1.72@62.25,17.05 62.25,16.199 62.17,16.119 62.17,9.226 65.275,6.121 65.275,5.478 65.275,3.9 65.75,3.425 66.125,3.425 66.391,3.691 J3.4@66.391,4.519
B2B_B2_L15_P: J3.3 JB1.70 | length 17.3
  L 01 (Top) w0.15: JB1.70@61.75,17.05 61.75,16.199 61.83,16.119 61.83,9.085 64.935,5.981 64.935,5.478 64.935,3.759 65.609,3.085 66.125,3.085 66.351,2.859 J3.3@66.351,1.979
B2B_B2_L18_N: J1.21 JB1.57 | length 43.9
  L 01 (Top) w0.15: JB1.57@58.75,20.75 58.768,20.732 v1@58.768,18.918
  L 04 (Bot) w0.15: J1.21@28.291,1.979 28.291,2.926 28.475,3.11 29.216,3.11 29.725,3.619 29.725,6.875 31.635,8.785 47.417,8.785 57.238,18.606 57.668,19.036 ; 57.996,19.036 cw(c57.996,18.264) v1@58.58,18.768 ; 58.323,19.036 cw(c58.323,18.547) v1@58.694,18.866 ; v1@58.467,18.67 ccw(c57.668,17.981) 57.668,19.036 ; v1@58.661,18.836 v1(58.675,18.85) ; v1@58.675,18.825 v1(58.675,18.85) ; 57.668,19.036 58.489,19.036 v1(58.675,18.85)
B2B_B2_L18_P: J1.22 JB1.55 | length 42.1
  L 01 (Top) w0.15: v1@57.958,19.845 ccw(c57.254,20.55) JB1.55@58.25,20.55 ; v1@58.064,19.739 ccw(c57.616,20.188) JB1.55@58.25,20.188 ; v1@58.25,19.825 JB1.55@58.25,20.75 ; 58.25,20.08 ccw(c58.582,20.08) v1@58.347,19.845
  L 04 (Bot) w0.15: J1.22@28.291,4.519 28.291,3.634 28.475,3.45 29.075,3.45 29.385,3.76 29.385,7.016 31.494,9.125 47.276,9.125 57.802,19.651 ; v1@57.886,19.586 ccw(c57.802,19.565) 57.802,19.651 ; v1@57.886,19.716 cw(c57.802,19.737) 57.802,19.651 ; v1(58.153,19.651) 57.802,19.651
B2B_B2_L21_N: J3.2 JB1.68 | length 16.4
  L 01 (Top) w0.15: JB1.68@61.25,17.05 61.25,16.259 61.355,16.154 61.355,4.646 62.551,3.45 63.7,3.45 63.851,3.601 J3.2@63.851,4.519
B2B_B2_L21_P: J3.1 JB1.66 | length 17.1
  L 01 (Top) w0.15: JB1.66@60.75,17.05 60.75,16.278 61.015,16.014 61.015,4.505 62.41,3.11 63.7,3.11 63.851,2.959 J3.1@63.851,1.979
B2B_B2_L29_N: J3.37 J7.5 JB1.91 R21.2 | length 65.2
  L 01 (Top) w0.15: JB1.91@67.25,20.75 67.25,21.7 67.45,21.9 85.628,21.9 88.758,18.77 98.58,18.77 99.775,19.965 J7.5@107.075,19.965 108.245,19.965 108.65,19.56 108.65,16.29 106.425,14.065 106.425,13.23 ; R21.2@105.4,13.23 106.425,13.23 ; J3.37@109.571,1.979 108.375,3.175 108.375,5.345 106.425,7.295 106.425,13.23
B2B_B2_L31_N: J3.17 JB1.76 | length 33.3
  L 01 (Top) w0.15: JB1.76@63.25,17.05 63.25,16.244 63.415,16.08 63.415,15.57 63.25,15.406 63.25,9.142 65.667,6.725 81.725,6.725 82.9,5.55 82.9,3.25 J3.17@84.171,1.979
B2B_B2_L32_N: J3.38 J7.3 JB1.31 R13.1 | length 83.6
  L 01 (Top) w0.15: 52.25,22.05 52.25,22.393 55.607,25.75 100.7,25.75 104.285,22.165 J7.3@107.075,22.165 109.585,22.165 111.4,20.35 111.4,15.3 110.773,14.673 109.873,14.673 108.3,13.1 108.3,6.199 109.571,4.929 J3.38@109.571,4.519 ; JB1.31@52.25,20.75 52.25,22.35 ; 108.34,6.85 R13.1@109.1,6.85
B2B_B2_L41_N: J1.38 JB1.60 | length 22.1
  L 01 (Top) w0.15: J1.38@48.611,4.519 48.611,3.589 48.825,3.375 53.675,3.375 59.142,8.842 59.142,16.163 59.25,16.271 JB1.60@59.25,17.05
B2B_B2_L41_P: J1.37 JB1.62 | length 22.6
  L 01 (Top) w0.15: J1.37@48.611,1.979 48.611,2.821 48.825,3.035 53.816,3.035 59.482,8.701 59.482,9.901 59.485,9.904 59.485,16.013 59.75,16.278 JB1.62@59.75,17.05
B2B_B2_L42_N: J3.36 J7.1 JB1.49 R19.2 | length 94.2
  L 01 (Top) w0.15: 73.85,23.445 v1@74.37,22.925 ; 73.85,24 R19.2@74.8,24 ; v1@74.29,22.925 v1@74.37,22.925 ; v1(74.4,22.925) v1@74.37,22.925 ; v1@105.89,24.365 J7.1@107.075,24.365 ; v1@106.069,24.156 cw(c106.575,23.65) J7.1@106.575,24.365 ; v1@106.069,24.544 ccw(c106.503,24.978) J7.1@106.503,24.365 ; 56.75,21.765 56.83,21.845 ; 56.75,21.765 56.83,21.844 ; 56.75,21.765 56.75,20.75 56.75,21.765 ; 56.83,21.845 56.83,24.236 57.714,25.12 73.186,25.12 73.765,24.541 73.765,23.53 v1@74.37,22.925 ; 73.879,23.416 ccw(c74.4,23.937) 74.4,23.2 cw(c74.4,23.937) 73.879,23.416 ; 73.952,23.343 cw(c73.534,22.925) 74.125,22.925 ccw(c73.534,22.925) 73.952,23.343 ; 74.135,23.16 ccw(c74.4,23.425) 74.4,23.05 cw(c74.4,23.425) 74.135,23.16
  L 04 (Bot) w0.15: 74.268,22.047 74.415,21.9 ; v1@74.287,22.674 cw(c74.209,22.5) 74.4,22.5 ; v1(74.4,22.925) 74.4,22.5 ; v1@74.513,22.674 ccw(c74.591,22.5) 74.4,22.5 ; v1@105.681,24.156 ccw(c105.211,23.686) 105.211,24.35 ccw(c105.211,25.014) v1@105.681,24.544 ; v1@106.025,24.35 106.4,24.35 ; J3.36@107.031,4.519 107.031,3.631 106.85,3.45 106.375,3.45 105.9,3.925 105.9,10.744 109.9,14.744 109.9,20.85 106.76,23.99 106.4,24.35 ; 74.4,22.5 74.265,22.365 74.265,22.05 74.415,21.9 ; 74.415,21.9 91.05,21.9 93.14,23.99 104.765,23.99 105.125,24.35 v1(105.875,24.35) 106.4,24.35 ; 106.4,24.35 cw(c106.4,24.714) 106.101,24.507 ccw(c106.4,24.714) 106.4,24.35 ; 106.4,24.35 ccw(c106.4,23.986) 106.101,24.193 cw(c106.4,23.986) 106.4,24.35
B2B_B2_L42_P: J3.35 J7.2 JB1.51 R18.2 | length 88.9
  L 01 (Top) w0.15: JB1.51@57.25,20.75 57.25,21.75 57.17,21.83 57.17,24.095 57.855,24.78 73.045,24.78 73.425,24.4 73.425,23.8 ; R18.2@72.45,23.8 73.425,23.8 ; v1@73.231,23.044 ccw(c72.761,23.514) 73.425,23.514 ccw(c74.089,23.514) v1@73.619,23.044 ; v1@73.425,22.873 73.425,23.8 ; v1(105.475,23.25) 106.66,23.25 J7.2@106.675,23.265 ; v1@105.669,23.056 cw(c106.139,22.586) 106.139,23.25 cw(c106.139,23.914) v1@105.669,23.444
  L 04 (Bot) w0.15: v1@73.425,22.575 cw(c73.425,21.911) 73.894,22.381 cw(c74.364,22.85) v1@73.7,22.85 ; v1(73.425,22.85) 73.925,22.35 73.925,21.909 74.274,21.56 91.191,21.56 93.281,23.65 104.6,23.65 105,23.25 ; v1@105.237,23.113 ccw(c105,22.977) 105,23.25 ; v1@105.237,23.387 cw(c105,23.523) 105,23.25 ; v1@105.669,23.056 cw(c106.139,22.586) 106.139,23.25 cw(c106.139,23.914) v1@105.669,23.444 ; J3.35@107.031,1.979 107.031,2.944 106.865,3.11 106.234,3.11 105.56,3.784 105.56,10.885 109.56,14.885 109.56,20.709 107.019,23.25 v1(105.475,23.25) 105,23.25
B2B_B2_L43_N: J1.36 JB1.56 | length 24
  L 01 (Top) w0.15: J1.36@46.071,4.519 46.071,3.554 46.225,3.4 46.725,3.4 47.21,3.885 47.21,5.166 47.922,5.877 54.477,5.877 58.33,9.73 58.33,16.119 58.25,16.199 JB1.56@58.25,17.05
B2B_B2_L43_P: J1.35 JB1.58 | length 24.5
  L 01 (Top) w0.15: J1.35@46.071,1.979 46.071,2.906 46.225,3.06 46.866,3.06 47.55,3.744 47.55,5.025 48.062,5.537 54.618,5.537 58.67,9.589 58.67,10.714 58.67,16.119 58.75,16.199 JB1.58@58.75,17.05
B2B_B2_L44_N: J1.20 JB1.45 | length 43.9
  L 01 (Top) w0.15: v1@55.356,19.669 ccw(c54.403,20.622) JB1.45@55.75,20.622 ; v1@55.462,19.563 ccw(c54.765,20.26) JB1.45@55.75,20.26 ; v1(55.55,19.475) 55.75,19.675 JB1.45@55.75,20.75 ; v1@55.568,19.457 ccw(c55.127,19.898) 55.75,19.898
  L 04 (Bot) w0.15: J1.20@25.751,4.519 25.751,3.674 26,3.425 26.475,3.425 26.91,3.86 26.91,6.841 30.244,10.175 46.794,10.175 55.55,18.931 ; v1@55.387,19.254 cw(c55.149,18.931) 55.55,18.931 ; v1(55.55,19.475) 55.55,18.931 ; v1@55.713,19.254 ccw(c55.951,18.931) 55.55,18.931
B2B_B2_L44_P: J1.19 JB1.47 | length 46.1
  L 01 (Top) w0.15: 56.25,19.715 ccw(c56.967,19.715) v1@56.46,19.208 ; 56.25,20.077 ccw(c57.329,20.077) v1@56.566,19.314 ; JB1.47@56.25,20.439 ccw(c57.691,20.439) v1@56.672,19.42 ; JB1.47@56.25,20.75 56.25,19.45 v1@56.525,19.175 ; v1(56.478,19.226) 56.503,19.201 v1@56.503,19.197
  L 04 (Bot) w0.15: J1.19@25.751,1.979 25.751,2.836 26,3.085 26.616,3.085 27.25,3.719 27.25,6.7 30.385,9.835 46.935,9.835 56.275,19.175 56.525,19.175 56.503,19.197 56.503,19.201 v1(56.478,19.226) ; 55.749,18.649 cw(c56.478,17.921) v1@56.478,18.951 ; 56.005,18.905 cw(c56.478,18.433) v1@56.478,19.101 ; 56.116,19.016 ccw(c55.905,19.226) v1@56.203,19.226
B2B_B2_L45_N: J1.34 JB1.50 | length 25.9
  L 01 (Top) w0.15: J1.34@43.531,4.519 43.531,3.644 43.775,3.4 44.2,3.4 44.635,3.835 44.635,5.76 45.627,6.752 53.752,6.752 57.5,10.5 57.5,15.2 56.85,15.85 56.85,16.2 56.75,16.3 JB1.50@56.75,17.05
B2B_B2_L45_P: J1.33 JB1.52 | length 26.4
  L 01 (Top) w0.15: J1.33@43.531,1.979 43.531,2.816 43.775,3.06 44.341,3.06 44.975,3.694 44.975,5.619 45.768,6.412 53.893,6.412 57.84,10.359 57.84,15.341 57.19,15.991 57.19,16.218 57.25,16.278 JB1.52@57.25,17.05
B2B_B2_L48_N: J1.32 JB1.46 | length 28
  L 01 (Top) w0.15: J1.32@40.991,4.519 40.991,3.559 41.175,3.375 41.575,3.375 42.11,3.91 42.11,7.241 42.547,7.678 52.877,7.678 56.7,11.5 56.7,14.55 55.83,15.42 55.83,16.119 55.75,16.199 JB1.46@55.75,17.05
B2B_B2_L48_P: J1.31 JB1.48 | length 28.5
  L 01 (Top) w0.15: J1.31@40.991,1.979 40.991,2.851 41.175,3.035 41.716,3.035 42.45,3.769 42.45,7.1 42.688,7.338 53.018,7.338 57.04,11.359 57.04,14.691 56.17,15.561 56.17,16.119 56.25,16.199 JB1.48@56.25,17.05
B2B_B2_L49_N: J1.16 JB1.36 | length 41.9
  L 01 (Top) w0.15: J1.16@20.671,4.519 20.671,3.629 20.9,3.4 21.35,3.4 21.76,3.81 21.76,6.741 23.26,8.241 35.491,8.241 37.25,10 47.7,10 53.325,15.625 53.325,16.131 53.25,16.206 JB1.36@53.25,17.05
B2B_B2_L49_P: J1.15 JB1.38 | length 42.4
  L 01 (Top) w0.15: J1.15@20.671,1.979 20.671,2.831 20.9,3.06 21.491,3.06 22.1,3.669 22.1,6.6 23.401,7.901 35.632,7.901 37.391,9.66 47.841,9.66 48.091,9.91 53.665,15.484 53.665,16.121 53.75,16.206 JB1.38@53.75,17.05
B2B_B2_L57_N: J1.14 JB1.32 | length 43
  L 01 (Top) w0.15: J1.14@18.131,4.519 18.131,3.544 18.275,3.4 18.825,3.4 19.26,3.835 19.26,6.26 22.588,9.588 34.513,9.588 35.975,11.05 47.53,11.05 52.33,15.85 52.33,16.126 52.25,16.206 JB1.32@52.25,17.05
B2B_B2_L57_P: J1.13 JB1.34 | length 43.6
  L 01 (Top) w0.15: J1.13@18.131,1.979 18.131,2.916 18.275,3.06 18.966,3.06 19.6,3.694 19.6,6.119 22.729,9.248 34.654,9.248 36.116,10.71 47.671,10.71 48.911,11.95 52.67,15.709 52.67,16.126 52.75,16.206 JB1.34@52.75,17.05
B2B_B2_L59_N: J1.10 JB1.39 | length 64.5
  L 01 (Top) w0.15: v1@53.88,22.549 cw(c53.31,21.71) 54.325,21.71 ; v1@53.965,22.673 cw(c53.503,21.993) 54.325,21.993 ; v1(54.035,22.776) 54.325,22.486 54.325,21.75 54.25,21.675 JB1.39@54.25,20.75 ; v1@54.049,22.797 cw(c53.695,22.276) 54.325,22.276 ; v1@54.133,22.921 cw(c53.888,22.559) 54.325,22.559
  L 04 (Bot) w0.15: J1.10@13.051,4.519 13.051,3.614 13.265,3.4 13.665,3.4 14.15,3.885 14.15,9.425 16.965,12.24 47.565,12.24 54.335,19.01 54.335,22.476 v1(54.035,22.776) ; v1@53.841,22.582 cw(c52.647,21.388) 54.335,21.388 ; v1@53.947,22.688 cw(c53.009,21.75) 54.335,21.75 ; v1@54.053,22.794 cw(c53.371,22.112) 54.335,22.112 ; v1@54.159,22.9 cw(c53.733,22.475) 54.335,22.475
B2B_B2_L59_P: J1.9 JB1.41 | length 59.8
  L 01 (Top) w0.15: JB1.41@54.675,20.825 54.75,20.75 54.75,21.7 54.675,21.775 54.675,22.45 54.975,22.75 v1(54.975,22.875) ; v1@54.753,22.713 cw(c54.628,22.622) 54.738,22.513 cw(c54.95,22.3) v1@54.963,22.6
  L 04 (Bot) w0.15: J1.9@13.051,1.979 13.051,2.846 13.265,3.06 13.806,3.06 14.49,3.744 14.49,9.284 17.106,11.9 47.706,11.9 54.675,18.869 54.675,22.45 54.975,22.75 v1(54.975,22.875) ; v1@54.753,22.713 cw(c54.628,22.622) 54.738,22.513 cw(c54.95,22.3) v1@54.963,22.6
B2B_B2_L60_N: J1.7 JB1.37 | length 58.5
  L 01 (Top) w0.15: v1(52.85,18.525) 53.75,19.425 JB1.37@53.75,20.75 ; v1@52.85,18.8 ccw(c52.85,19.464) 53.319,18.994 ccw(c53.789,18.525) v1@53.125,18.525
  L 04 (Bot) w0.15: J1.7@10.511,1.979 10.511,2.846 10.725,3.06 11.266,3.06 11.95,3.744 11.95,8.869 16.131,13.05 39.625,13.05 45.66,19.085 51.955,19.085 52.515,18.525 v1(52.85,18.525) ; 52.123,18.918 ccw(c52.543,19.338) v1@52.753,18.782 ; 52.287,18.754 ccw(c52.633,19.099) v1@52.806,18.642 ; 52.451,18.589 ccw(c52.723,18.861) v1@52.859,18.502
B2B_B2_L60_P: J1.8 JB1.35 | length 56.5
  L 01 (Top) w0.15: v1(52.725,19.425) 53.25,19.95 JB1.35@53.25,20.75 ; v1@52.725,19.7 ccw(c52.725,20.364) 53.194,19.894 ccw(c53.664,19.425) v1@53,19.425
  L 04 (Bot) w0.15: J1.8@10.511,4.519 10.511,3.614 10.725,3.4 11.125,3.4 11.61,3.885 11.61,9.01 15.99,13.39 39.484,13.39 45.519,19.425 v1(52.725,19.425) ; v1@52.531,19.231 ccw(c52.061,18.761) 52.061,19.425 ccw(c52.061,20.089) v1@52.531,19.619
B2B_B3_L9_N: J2.12 JB2.22 R17.2 | length 69.8
  L 01 (Top) w0.15: R17.2@29.15,42.05 v1(30.025,42.05) ; v1@29.831,41.856 ccw(c29.361,41.386) 29.361,42.05 ccw(c29.361,42.714) v1@29.831,42.244 ; v1@49.677,47.689 ccw(c49.371,48.061) 49.852,48.061 ; JB2.22@49.75,48.85 49.75,48.163 49.852,48.061 ; v1(49.852,47.477) 49.852,48.061 ; v1@50.027,47.689 cw(c50.334,48.061) 49.852,48.061
  L 04 (Bot) w0.15: J2.12@15.591,68.019 15.591,67.099 15.75,66.94 16.241,66.94 17.04,66.141 17.04,44.311 20.026,41.325 30.025,41.325 ; v1@29.831,41.856 cw(c29.361,41.386) 30.025,41.386 cw(c30.689,41.386) v1@30.219,41.856 ; v1(30.025,42.05) 30.025,41.325 ; v1@49.725,47.234 cw(c49.614,47.023) 49.852,47.023 ; v1(49.852,47.477) 49.852,47.023 ; v1@49.98,47.234 ccw(c50.091,47.023) 49.852,47.023 ; 30.025,41.325 46.5,41.325 50.4,45.225 50.4,46.475 49.852,47.023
